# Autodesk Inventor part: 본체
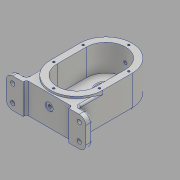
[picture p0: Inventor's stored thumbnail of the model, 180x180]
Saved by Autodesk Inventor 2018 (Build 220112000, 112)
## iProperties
Created: 2021-05
Part Number: 본체
Material: 알루미늄 6061
Document SubType Name: Modeling
Designer: admin
Density: 2.7 g/cm^3
Appearance: 알루미늄 - 평지
Mass: 752.793 g
Surface Area: 587.908 cm^2
Volume: 278.812 cm^3
Author: admin
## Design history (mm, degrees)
sketch "스케치1"
  geometry: L1 (0, -14.8)-(0, 88.8) reference; L2 (-85.4, 0)-(85.4, 0) reference; L3 (-61, 0)-(-61, 10); L4 (-61, 10)-(-40, 10); L5 (-40, 10)-(-40, 74); L6 (-40, 74)-(0, 74); L7 (-61, 0)-(-35, 0); L8 (-35, 0)-(-35, 5); L9 (-35, 5)-(0, 5); L10 (35, 5)-(0, 5); L11 (35, 0)-(35, 5); L12 (61, 0)-(35, 0); L13 (61, 0)-(61, 10); L14 (61, 10)-(40, 10); L15 (40, 10)-(40, 74); L16 (40, 74)-(0, 74); 1 further point
  constraints: 28 end point, 6 symmetric about line, 4 perpendicular, 4 point on line, 2 vertical
  dimensions: "d3" = 61 distance of point (0, 0) L3.start; "d4" = 10 distance of L3.start L3.end; "d5" = 35 distance from line of L9.end L8; "d6" = 5 distance of L7.end L8.end; "d7" = 40 distance between parallel lines of L1 L5; "d8" = 74 distance between parallel lines of L6 L2
extrude "돌출1" new body sketch "스케치1" stored distance "d9" = 46; taper "d10" = 0 deg
node "작업 평면1"
sketch "스케치2"
  geometry: L1 (-61, 10)-(-61, 0) reference; L2 (-61, 0)-(-35, 0) reference; L3 (-35, 0)-(-35, 5) reference; L4 (-35, 5)-(35, 5) reference; L5 (35, 5)-(35, 0) reference; L6 (35, 0)-(61, 0) reference; L7 (61, 0)-(61, 10) reference; L8 (61, 10)-(40, 10) reference; L9 (40, 10)-(40, 74) reference; L10 (40, 74)-(-40, 74) reference; L11 (-40, 74)-(-40, 10) reference; L12 (-40, 10)-(-61, 10) reference; L13 (-40, 92)-(40, 92); L14 (40, 92)-(40, 47); L15 (40, 47)-(-40, 47); L16 (-40, 47)-(-40, 92); C1 r 40 at (0, 47); 2 further points
  constraints: 8 end point, 2 midpoint, 2 parallel, 2 tangent, 1 centre point, 1 horizontal, 1 horizontal alignment, 1 perpendicular, 2 other
  dimensions: "d12" = 47 distance from line of C1.centre L6; "d13" = 80 diameter of C1; "d14" = 80 distance of L13.start L13.end; "d15" = 45 distance of L13.end L14.end
extrude "돌출2" join sketch "스케치2" distance "d16" = 49; taper "d17" = 0 deg
sketch "스케치3"
  geometry: L1 (0, -26.4)-(0, 158.4) reference; L2 (85.4, 0)-(-85.4, 0) reference; L3 (26, 47)-(26, 92); L4 (-26, 92)-(-26, 47); A1 r 26 centre (0, 47) between (26, 47) and (-26, 47); A2 r 26 centre (0, 92) between (26, 92) and (-26, 92); 1 further point
  constraints: 4 end point, 4 point on circle, 2 centre point, 2 point on line, 2 tangent, 2 vertical
  dimensions: "d18" = 52 diameter of A1; "d19" = 47 distance from line of A1.centre L2; "d20" = 52 diameter of A2; "d21" = 45 distance of A2.centre A1.centre
extrude "돌출3" join sketch "스케치3" distance "d22" = 11; taper "d23" = 0 deg
sketch "스케치4"
  geometry: L1 (-26, 92)-(-26, 47) reference; L2 (26, 47)-(26, 92) reference; L3 (26, 92)-(26, 47) reference; L4 (26, 92)-(26, 62); L5 (26, 62)-(-26, 62); L6 (-26, 62)-(-26, 92); A1 r 26 centre (0, 92) between (26, 92) and (-26, 92) reference; A2 r 26 centre (0, 47) between (-26, 47) and (26, 47) reference; A3 r 26 centre (0, 92) between (26, 92) and (-26, 92) reference; A4 r 26 centre (0, 92) between (26, 92) and (-26, 92); 1 further point
  constraints: 6 end point, 3 point on circle, 1 centre point, 1 coincident, 1 parallel, 1 point on line
  dimensions: "d24" = 30 distance from line of L5 A1.centre; "d25" = 52 distance of L4.end L5.end; "d26" = 30 distance of L5.end L1.start
extrude "돌출4" cut sketch "스케치4" distance "d27" = 3; taper "d28" = 0 deg
sketch "스케치5"
  geometry: L1 (0, -26.4)-(0, 158.4) reference; L2 (85.4, 0)-(-85.4, 0) reference; 2 further points
  constraints: 1 point on line, 1 other
  dimensions: "d29" = 12 distance from line of point (0, 12) L2
feature "엠보싱1" sketch "스케치5" dims "d30" = 0.5, "d31" = 0
sketch "스케치6"
  geometry: L1 (-40, 47)-(-40, 92) reference; L2 (40, 92)-(40, 47) reference; L3 (30, 92)-(30, 47); L4 (-30, 92)-(-30, 47); A1 r 40 centre (0, 92) between (40, 92) and (-40, 92) reference; A2 r 40 centre (0, 47) between (-40, 47) and (40, 47) reference; A3 r 30 centre (0, 92) between (-30, 92) and (30, 92); A4 r 30 centre (0, 47) between (-30, 47) and (30, 47); 1 further point
  constraints: 4 end point, 4 point on circle, 2 centre point, 2 coincident, 2 tangent, 2 vertical
  dimensions: "d32" = 60 diameter of A3; "d33" = 60 diameter of A4
extrude "돌출5" cut sketch "스케치6" distance "d35" = 41; taper "d36" = 0 deg
sketch "스케치7"
  geometry: L1 (30, 92)-(30, 47) reference; L2 (-30, 47)-(-30, 92) reference; C1 r 14 at (0, 92); C2 r 14 at (0, 47); A1 r 30 centre (0, 92) between (30, 92) and (-30, 92) reference; A2 r 30 centre (0, 47) between (-30, 47) and (30, 47) reference; 1 further point
  constraints: 2 centre point, 2 coincident
  dimensions: "d37" = 28 diameter of C1; "d38" = 28 diameter of C2
extrude "돌출6" cut sketch "스케치7" distance "d39" = 8; taper "d40" = 0 deg
sketch "스케치8"
  geometry: C1 r 14 at (0, 0) reference; C2 r 14 at (0, -45) reference; C3 r 11 at (0, 0); 1 further point
  constraints: 1 centre point, 1 coincident
  dimensions: "d41" = 22 diameter of C3
extrude "돌출7" cut sketch "스케치8" stored distance "d42" = 8; taper "d43" = 0 deg
sketch "스케치9"
  geometry: C1 r 11 at (0, 92) reference; C2 r 14 at (0, 92); 1 further point
  constraints: 1 centre point, 1 coincident
  dimensions: "d44" = 28 diameter of C2
extrude "돌출8" cut sketch "스케치9" distance "d45" = 4; taper "d46" = 0 deg
sketch "스케치10"
  geometry: C1 r 14 at (0, 0) reference; C2 r 10 at (0, 0); 1 further point
  constraints: 1 centre point, 1 coincident
  dimensions: "d47" = 20 diameter of C2
extrude "돌출9" cut sketch "스케치10" distance "d48" = 4; taper "d49" = 0 deg
node "작업 평면2"
sketch "스케치11"
  geometry: L1 (-40, 26)-(40, 26) reference; L2 (0, -46)-(0, 38) reference; C1 r 6 at (0, 5); 1 further point
  constraints: 1 centre point, 1 point on line
  dimensions: "d51" = 12 diameter of C1; "d52" = 21 distance from line of C1.centre L1
extrude "돌출10" join sketch "스케치11" distance "d53" = 4; taper "d54" = 0 deg
sketch "스케치12"
  geometry: C1 r 6 at (0, 0) reference; C2 r 2.293 at (0, 0); 1 further point
  constraints: 1 centre point, 1 coincident
hole "구멍1" sketch "스케치12" at (0, 0) diameter "d55" = 4.917; stored, may be unused: countersink angle "d59" = 90 deg, drill point angle "d61" = 118 deg; dims "d56" = 138, "d57" = 4, "d58" = 2, "d60" = 140
sketch "스케치13"
  geometry: C1 r 2.458 at (35, -18) reference; C2 r 6 at (35, -18); 1 further point
  constraints: 1 centre point, 1 coincident
  dimensions: "d62" = 12 diameter of C2
extrude "돌출11" cut sketch "스케치13" distance "d63" = 1; taper "d64" = 0 deg
fillet "모깎기1" dims "d65" = 10
sketch "스케치15" dims "d66" = 40
  geometry: L1 (-26, 62)-(-26, 92) reference; L2 (26, 62)-(-26, 62) reference; L3 (26, 92)-(26, 62) reference; C1 r 14 at (0, 92) reference; C2 r 3.851 at (0, 112); A1 r 26 centre (0, 92) between (26, 92) and (-26, 92) reference; 2 further points
  constraints: 1 centre point, 1 coincident, 1 vertical alignment, 2 other
hole "구멍2" sketch "스케치15" at (0, 112) diameter "d67" = 3.242; stored, may be unused: countersink angle "d71" = 90 deg, drill point angle "d73" = 118 deg; dims "d68" = 8, "d69" = 4, "d70" = 2, "d72" = 10
sketch "스케치16"
  geometry: L1 (-21, 10)-(-21, 36) reference; L2 (0, 0)-(-11, 0) reference; L3 (0, 0)-(0, 46) reference; L4 (-11, 46)-(0, 46) reference; L5 (80, 46)-(91, 46) reference; L6 (80, 0)-(80, 46) reference; L7 (91, 0)-(80, 0) reference; L8 (101, 10)-(101, 36) reference; C1 r 5.5 at (-11, 36); A1 r 10 centre (-11, 36) between (-11, 46) and (-21, 36) reference; A2 r 10 centre (-11, 10) between (-21, 10) and (-11, 0) reference; A3 r 10 centre (91, 36) between (101, 36) and (91, 46) reference; A4 r 10 centre (91, 10) between (91, 0) and (101, 10) reference; 1 further point
  constraints: 1 centre point, 1 coincident
  dimensions: "d77" = 11 diameter of C1
extrude "돌출12" cut sketch "스케치16" distance "d78" = 2; taper "d79" = 0 deg
sketch "스케치17"
  geometry: L1 (-10, -26)-(-10, 0) reference; L2 (11, -36)-(0, -36) reference; L3 (11, -36)-(11, 10) reference; L4 (0, 10)-(11, 10) reference; C1 r 5.5 at (0, 0) reference; C2 r 3.3 at (0, 0); A1 r 10 centre (0, 0) between (0, 10) and (-10, 0) reference; A2 r 10 centre (0, -26) between (-10, -26) and (0, -36) reference; 1 further point
  constraints: 1 centre point, 1 coincident
  dimensions: "d80" = 6.6 diameter of C2
extrude "돌출13" cut sketch "스케치17" stored distance "d81" = 2; taper "d82" = 0 deg
sketch "스케치18"
  geometry: L1 (30, 92)-(30, 47) reference; L2 (-30, 47)-(-30, 92) reference; L3 (-40, 47)-(-40, 92) reference; L4 (40, 92)-(40, 47) reference; L5 (35, 92)-(35, 47); L6 (-35, 92)-(-35, 47); L7 (0, -27)-(0, 162) reference; L8 (0.027, 9.908)-(0.027, 13.577) reference; L9 (-35, 47)-(35, 47); L10 (-35, 92)-(35, 92); C1 r 3.66 at (0, 127); C2 r 3.899 at (0.027, 11.742); C3 r 3.659 at (35, 92); C4 r 3.592 at (35, 47); C5 r 3.193 at (-35, 92); C6 r 2.901 at (-35, 47); A1 r 30 centre (0, 92) between (30, 92) and (-30, 92) reference; A2 r 30 centre (0, 47) between (-30, 47) and (30, 47) reference; A3 r 40 centre (0, 92) between (40, 92) and (-40, 92) reference; A4 r 40 centre (0, 47) between (-40, 47) and (40, 47) reference; A5 r 35 centre (0, 92) between (35, 92) and (-35, 92); A6 r 35 centre (0, 47) between (35, 47) and (-35, 47); 1 further point
  constraints: 8 centre point, 8 end point, 6 coincident, 5 point on circle, 2 horizontal, 2 tangent, 2 vertical, 1 midpoint, 1 point on line
  dimensions: "d83" = 70 diameter of A5; "d84" = 70 diameter of A6
hole "구멍3" sketch "스케치18" at (0, 127), (0.027, 11.742), (35, 47), (35, 92), (-35, 92), (-35, 47) diameter "d86" = 3.242; stored, may be unused: countersink angle "d90" = 90 deg, drill point angle "d92" = 118 deg; dims "d87" = 8, "d88" = 4, "d89" = 2, "d91" = 10
fillet "모깎기2" dims "d93" = 0.3
chamfer "모따기1" distance "d94" = 1; stored, may be unused: second distance "d95" = 2, angle "d96" = 45 deg
chamfer "모따기2" distance "d97" = 1; stored, may be unused: second distance "d98" = 2, angle "d99" = 45 deg
fillet "모깎기3" dims "d100" = 3
fillet "모깎기4" dims "d101" = 3
fillet "모깎기5" dims "d102" = 3
fillet "모깎기6" dims "d103" = 3
fillet "모깎기7" dims "d104" = 3
node "솔리드1"
pattern_circular "원형 패턴1" dims angle "d75" = 360 deg
mirror "미러1"
mirror "미러2"
node "투영된 루프1"
node "투영된 루프2"
node "투영된 루프3"
node "투영된 루프4"
node "투영된 루프5"
node "투영된 루프6"
node "투영된 루프7"
node "투영된 루프8"
node "투영된 루프9"
node "투영된 루프10"
node "투영된 루프11"
node "투영된 루프12"
node "투영된 루프13"
other parameters: "d11" = 26, "d50" = 135
